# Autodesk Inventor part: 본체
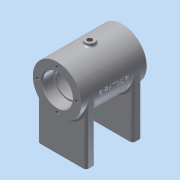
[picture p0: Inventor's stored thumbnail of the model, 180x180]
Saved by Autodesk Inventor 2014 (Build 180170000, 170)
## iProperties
Created: 2020-07
Part Number: 본체
Material: Aluminum 6061
Document SubType Name: Modeling
Designer: kh
Density: 2.71 g/cm^3
Appearance: Aluminum - Flat
Mass: 306.378 g
Surface Area: 357.568 cm^2
Volume: 113.054 cm^3
Author: kh
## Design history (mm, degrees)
sketch "Sketch1"
  geometry: C1 r 26 at (64, 0); 1 further point
  constraints: 1 centre point
  dimensions: "d0" = 52 diameter of C1; "d1" = 64 distance of point (0, 0) C1.centre
extrude "Extrusion1" new body sketch "Sketch1" stored distance "d2" = 70; taper "d3" = 0 deg
sketch "Sketch2"
  geometry: L1 (-35, 90)-(-35, 38) reference; L2 (35, 38)-(35, 90) reference; L3 (-35, 64)-(35, 64); L4 (-35, 64)-(-35, 80); L5 (-35, 80)-(-23, 80); L6 (-23, 80)-(-23, 78); L7 (-23, 78)-(-21, 78); L8 (-21, 78)-(-21, 85); L9 (-21, 85)-(21, 85); L10 (21, 85)-(21, 78); L11 (21, 78)-(23, 78); L12 (23, 78)-(23, 80); L13 (23, 80)-(35, 80); 2 further points
  constraints: 22 end point, 4 parallel, 4 perpendicular, 3 collinear, 3 midpoint, 2 point on line
  dimensions: "d4" = 32 diameter of L5 L3; "d5" = 28 diameter of L7 L3; "d6" = 42 distance of L8.end L9.end; "d7" = 2 distance of L6.end L7.end; "d8" = 12 distance of L4.end L5.end; "d9" = 42 diameter of L9 L3; "d10" = 12 distance of L12.end L13.end
revolve "Revolution1" sketch "Sketch2" stored, may be unused: angle "d11" = 90 deg
workplane "Work Plane1"
sketch "Sketch3"
  geometry: L1 (64, 26)-(0, 26); L2 (0, 26)-(0, -26); L3 (0, -26)-(64, -26); L4 (64, -26)-(64, 26); A1 r 26 centre (64, 0) between (64, 26) and (64, -26) reference; 1 further point
  constraints: 8 end point, 2 point on circle, 2 tangent, 1 horizontal, 1 perpendicular
  dimensions: "d13" = 52 distance of L1.end L2.end
extrude "Extrusion2" join sketch "Sketch3" distance "d14" = 10; taper "d15" = 0 deg
workplane "Work Plane2"
sketch "Sketch4"
  geometry: L1 (64, -26)-(0, -26); L2 (0, -26)-(0, 26); L3 (0, 26)-(64, 26); A1 r 26 centre (64, 0) between (64, 26) and (64, -26) reference; 1 further point
  constraints: 6 end point, 1 horizontal, 1 parallel, 1 perpendicular, 1 point on circle, 1 tangent
extrude "Extrusion3" join sketch "Sketch4" distance "d17" = 10; taper "d18" = 0 deg
workplane "Work Plane3"
sketch "Sketch5"
  geometry: L1 (0, 0)-(0, -34); L2 (0, 0)-(-11.203, -30.781); L3 (-7.498, -20.6)-(-13.136, -18.548); L4 (-13.136, -18.548)-(-15.557, -25.199); L5 (-15.557, -25.199)-(-9.919, -27.251); L6 (-4.649, -30.316)-(-13.136, -18.548); L7 (-1.142, -23.54)-(-15.557, -25.199); A1 r 26 centre (0, 0) between (-26, 0) and (26, 0) reference; 2 further points
  constraints: 14 end point, 4 point on line, 1 midpoint, 1 parallel, 1 perpendicular, 1 point on circle, 1 vertical
  dimensions: "d20" = 20 deg angle of L1 L2; "d23" = 29 distance from line of L1.start L5
revolve "Revolution2" sketch "Sketch5" stored, may be unused: angle "d24" = 90 deg
sketch "Sketch6"
  geometry: L1 (0, 23)-(-5, 23); L2 (-5, 23)-(-5, 29); L3 (-5, 29)-(0, 29); L4 (5, 23)-(-5, 29); L5 (-5, 23)-(5, 29); L6 (0, 29)-(0, 23); 3 further points
  constraints: 12 end point, 2 midpoint, 1 horizontal, 1 parallel, 1 perpendicular, 1 vertical alignment, 1 other
  dimensions: "d25" = 10 distance of L2.end L5.end; "d26" = 3 distance from line of point (0, 26) L3
revolve "Revolution3" sketch "Sketch6" stored, may be unused: angle "d27" = 90 deg
sketch "Sketch7"
  geometry: 2 further points
hole "Hole1" sketch "Sketch7" at (0, 21) diameter "d29" = 3.242; stored, may be unused: countersink angle "d33" = 90 deg, drill point angle "d35" = 118 deg; dims "d30" = 8, "d31" = 4, "d32" = 2, "d34" = 10
pattern_circular "Circular Pattern1" dims angle "d37" = 360 deg
mirror "Mirror1"
workplane "Work Plane5"
sketch "Sketch9"
  geometry: L1 (-10, 0)-(-10, 52) reference; L2 (-10, 26)-(50, 26); L3 (0, 0)-(-10, 0) reference; 2 further points
  constraints: 2 end point, 1 midpoint, 1 perpendicular
  dimensions: "d41" = 5 distance from line of L1 point (-5, 46); "d42" = 26 distance between parallel lines of L3 L2; "d43" = 20 distance from line of L2 point (-5, 46)
hole "Hole2" sketch "Sketch9" at (-5, 46) diameter "d44" = 4.134; stored, may be unused: countersink angle "d48" = 90 deg, drill point angle "d50" = 118 deg; dims "d45" = 8, "d46" = 4, "d47" = 2, "d49" = 10
pattern_linear "Rectangular Pattern1" dims "d53" = 40
sketch "Sketch10"
  geometry: 2 further points
hole "Hole3" sketch "Sketch10" at (5, 46) diameter "d54" = 4.134; stored, may be unused: countersink angle "d58" = 90 deg, drill point angle "d60" = 118 deg; dims "d55" = 8, "d56" = 4, "d57" = 2, "d59" = 10
pattern_linear "Rectangular Pattern2" dims "d63" = 40
hole "Hole4" diameter "d66" = 5.188; stored, may be unused: countersink angle "d70" = 90 deg, drill point angle "d72" = 118 deg; dims "d64" = 10, "d65" = 10, "d67" = 8, "d68" = 4, "d69" = 2, "d71" = 18.25
sketch "Sketch11"
  geometry: C1 r 6 at (0, 0) reference; 1 further point
hole "Hole5" diameter "d75" = 5.188; stored, may be unused: countersink angle "d79" = 90 deg, drill point angle "d81" = 118 deg; dims "d73" = 10, "d74" = 10, "d76" = 8, "d77" = 4, "d78" = 2, "d80" = 18.25
workplane "Work Plane7"
sketch "Sketch12"
  geometry: L1 (-35, 26)-(-35, -26) reference; L2 (-35, 26)-(35, 26) reference; 2 further points
  constraints: 1 other
  dimensions: "d82" = 35 distance from line of L1 point (0, 0); "d83" = 26 distance from line of point (0, 0) L2
emboss "Emboss1" sketch "Sketch12" dims "d12" = 20, "d84" = 0.5, "d85" = 0
fillet "Fillet1" dims "d86" = 0.3
fillet "Fillet2" dims "d87" = 3
fillet "Fillet3" dims "d88" = 3
fillet "Fillet4" dims "d89" = 3
fillet "Fillet5" dims "d90" = 2
chamfer "Chamfer1" distance "d91" = 1; stored, may be unused: second distance "d92" = 2, angle "d93" = 45 deg
body "Solid1"
workplane "Work Plane4"
other parameters: "d19" = -35
